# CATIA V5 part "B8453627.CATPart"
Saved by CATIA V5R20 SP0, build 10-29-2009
Part number: B8453627
Revision: 2
Definition: design
Nomenclature: B8453627
Source: made
Description: NOT SPECIFIED
Bounding box of the stored display mesh (mm): x -29 to 29, y -29 to 29, z -22 to 27
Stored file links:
  C:\Users\Utente\Desktop\3D files B845\B8453627.CATPart
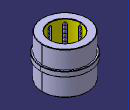
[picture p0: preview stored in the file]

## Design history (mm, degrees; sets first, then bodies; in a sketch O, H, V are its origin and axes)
Body1 "MANIFOLD_SOLID_BREP #38" (main body)
  Solid1: solid without history
Body2 "MANIFOLD_SOLID_BREP #76"
  Solid2: solid without history
Body3 "MANIFOLD_SOLID_BREP #114"
  Solid3: solid without history
Body4 "MANIFOLD_SOLID_BREP #152"
  Solid4: solid without history
Body5 "MANIFOLD_SOLID_BREP #190"
  Solid5: solid without history
Body6 "MANIFOLD_SOLID_BREP #2290"
  Solid6: solid without history
Body7 "MANIFOLD_SOLID_BREP #2328"
  Solid7: solid without history
Body8 "MANIFOLD_SOLID_BREP #2366"
  Solid8: solid without history
Body9 "MANIFOLD_SOLID_BREP #2404"
  Solid9: solid without history
Body10 "MANIFOLD_SOLID_BREP #2442"
  Solid10: solid without history
Body11 "MANIFOLD_SOLID_BREP #2480"
  Solid11: solid without history
Body12 "MANIFOLD_SOLID_BREP #2518"
  Solid12: solid without history
Body13 "MANIFOLD_SOLID_BREP #2556"
  Solid13: solid without history
Body14 "MANIFOLD_SOLID_BREP #2594"
  Solid14: solid without history
Body15 "MANIFOLD_SOLID_BREP #2632"
  Solid15: solid without history
Body16 "MANIFOLD_SOLID_BREP #2670"
  Solid16: solid without history
Body17 "MANIFOLD_SOLID_BREP #2708"
  Solid17: solid without history
Body18 "MANIFOLD_SOLID_BREP #2746"
  Solid18: solid without history
Body19 "MANIFOLD_SOLID_BREP #2784"
  Solid19: solid without history
Body20 "MANIFOLD_SOLID_BREP #2822"
  Solid20: solid without history
Body21 "MANIFOLD_SOLID_BREP #2860"
  Solid21: solid without history
Body22 "MANIFOLD_SOLID_BREP #2898"
  Solid22: solid without history
Body23 "MANIFOLD_SOLID_BREP #2936"
  Solid23: solid without history
Body24 "MANIFOLD_SOLID_BREP #2974"
  Solid24: solid without history
Body25 "MANIFOLD_SOLID_BREP #3012"
  Solid25: solid without history
Body26 "MANIFOLD_SOLID_BREP #3050"
  Solid26: solid without history
Body27 "MANIFOLD_SOLID_BREP #3088"
  Solid27: solid without history
Body28 "MANIFOLD_SOLID_BREP #3126"
  Solid28: solid without history
Body29 "MANIFOLD_SOLID_BREP #3164"
  Solid29: solid without history
Body30 "MANIFOLD_SOLID_BREP #3202"
  Solid30: solid without history
Body31 "MANIFOLD_SOLID_BREP #3240"
  Solid31: solid without history
Body32 "MANIFOLD_SOLID_BREP #3278"
  Solid32: solid without history
Body33 "MANIFOLD_SOLID_BREP #3316"
  Solid33: solid without history
Body34 "MANIFOLD_SOLID_BREP #3354"
  Solid34: solid without history
Body35 "MANIFOLD_SOLID_BREP #3392"
  Solid35: solid without history
Body36 "MANIFOLD_SOLID_BREP #3430"
  Solid36: solid without history
Body37 "MANIFOLD_SOLID_BREP #3468"
  Solid37: solid without history
Body38 "MANIFOLD_SOLID_BREP #3506"
  Solid38: solid without history
Body39 "MANIFOLD_SOLID_BREP #3544"
  Solid39: solid without history
Body40 "MANIFOLD_SOLID_BREP #3582"
  Solid40: solid without history
Body41 "MANIFOLD_SOLID_BREP #3620"
  Solid41: solid without history
Body42 "MANIFOLD_SOLID_BREP #3658"
  Solid42: solid without history
Body43 "MANIFOLD_SOLID_BREP #3696"
  Solid43: solid without history
Body44 "MANIFOLD_SOLID_BREP #3734"
  Solid44: solid without history
Body45 "MANIFOLD_SOLID_BREP #3772"
  Solid45: solid without history
Body46 "MANIFOLD_SOLID_BREP #3810"
  Solid46: solid without history
Body47 "MANIFOLD_SOLID_BREP #3848"
  Solid47: solid without history
Body48 "MANIFOLD_SOLID_BREP #3886"
  Solid48: solid without history
Body49 "MANIFOLD_SOLID_BREP #3924"
  Solid49: solid without history
Body50 "MANIFOLD_SOLID_BREP #3962"
  Solid50: solid without history
Body51 "MANIFOLD_SOLID_BREP #4000"
  Solid51: solid without history
Body52 "MANIFOLD_SOLID_BREP #4038"
  Solid52: solid without history
Body53 "MANIFOLD_SOLID_BREP #4076"
  Solid53: solid without history
Body54 "MANIFOLD_SOLID_BREP #4114"
  Solid54: solid without history
Body55 "MANIFOLD_SOLID_BREP #4152"
  Solid55: solid without history
Body56 "MANIFOLD_SOLID_BREP #4190"
  Solid56: solid without history
Body57 "MANIFOLD_SOLID_BREP #4228"
  Solid57: solid without history
Body58 "MANIFOLD_SOLID_BREP #4266"
  Solid58: solid without history
Body59 "MANIFOLD_SOLID_BREP #4304"
  Solid59: solid without history
Body60 "MANIFOLD_SOLID_BREP #4342"
  Solid60: solid without history
Body61 "MANIFOLD_SOLID_BREP #4380"
  Solid61: solid without history
Body62 "MANIFOLD_SOLID_BREP #4418"
  Solid62: solid without history
Body63 "MANIFOLD_SOLID_BREP #4456"
  Solid63: solid without history
Body64 "MANIFOLD_SOLID_BREP #4494"
  Solid64: solid without history
Body65 "MANIFOLD_SOLID_BREP #4532"
  Solid65: solid without history
Body66 "MANIFOLD_SOLID_BREP #4570"
  Solid66: solid without history
Body67 "MANIFOLD_SOLID_BREP #4608"
  Solid67: solid without history
Body68 "MANIFOLD_SOLID_BREP #4646"
  Solid68: solid without history
Body69 "MANIFOLD_SOLID_BREP #4684"
  Solid69: solid without history
Body70 "MANIFOLD_SOLID_BREP #4722"
  Solid70: solid without history
Body71 "MANIFOLD_SOLID_BREP #4760"
  Solid71: solid without history
Body72 "MANIFOLD_SOLID_BREP #4798"
  Solid72: solid without history
Body73 "MANIFOLD_SOLID_BREP #4836"
  Solid73: solid without history
Body74 "MANIFOLD_SOLID_BREP #4874"
  Solid74: solid without history
Body75 "MANIFOLD_SOLID_BREP #4912"
  Solid75: solid without history
Body76 "MANIFOLD_SOLID_BREP #4950"
  Solid76: solid without history
Body77 "MANIFOLD_SOLID_BREP #4988"
  Solid77: solid without history
Body78 "MANIFOLD_SOLID_BREP #5026"
  Solid78: solid without history
Body79 "MANIFOLD_SOLID_BREP #5064"
  Solid79: solid without history
Body80 "MANIFOLD_SOLID_BREP #5102"
  Solid80: solid without history
Body81 "MANIFOLD_SOLID_BREP #5140"
  Solid81: solid without history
